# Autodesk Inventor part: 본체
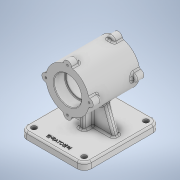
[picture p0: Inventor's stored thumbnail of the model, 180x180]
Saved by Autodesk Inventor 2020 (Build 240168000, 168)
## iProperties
Created: 2022-11
Part Number: 본체
Material: 일반
Document SubType Name: Modeling
Designer: owner
Density: 1 g/cm^3
Appearance: 기본값
Mass: 448.497 g
Surface Area: 803.898 cm^2
Volume: 448.497 cm^3
Author: owner
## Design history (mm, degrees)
sketch "스케치1"
  geometry: L1 (55, 65)-(-55, 65); L2 (-55, 65)-(-55, -65); L3 (-55, -65)-(55, -65); L4 (55, -65)-(55, 65); L5 (55, 65)-(-55, -65); L6 (-55, 65)-(55, -65); 1 further point
  constraints: 12 end point, 2 midpoint, 2 parallel, 1 horizontal, 1 perpendicular
  dimensions: "d0" = 110 distance of L3.end L2.end; "d1" = 130 distance of L2.end L1.end
extrude "돌출1" new body sketch "스케치1" distance "d2" = 12; taper "d3" = 0 deg
node "작업 평면1"
sketch "스케치6"
  geometry: L1 (0, 0)-(110, 0) reference; C1 r 37 at (55, 82); 2 further points
  constraints: 1 centre point, 1 midpoint, 1 vertical alignment
  dimensions: "d20" = 82 distance from line of L1 C1.centre; "d86" = 74 diameter of C1
extrude "돌출4" join sketch "스케치6" stored distance "d21" = 87; taper "d22" = 0 deg
sketch "스케치7"
  geometry: L1 (80.336, 55.036)-(96, 12); L2 (0, 12)-(110, 12) reference; L3 (110, 0)-(110, 12) reference; L4 (29.664, 55.036)-(14, 12); L5 (0, 0)-(0, 12) reference; A1 r 37 centre (55, 82) between (80.336, 55.036) and (29.664, 55.036) reference; 3 further points
  constraints: 4 end point, 2 point on circle
  dimensions: "d23" = 70 deg angle of L2 L1; "d24" = 0 distance from line of L2 L1.end; "d25" = 14 distance from line of L3 L1.end; "d26" = 70 deg angle of L2 L4; "d27" = 14 distance from line of L5 L4.end; "d28" = 0 distance from line of L2 L4.end
extrude "돌출5" join sketch "스케치7" stored distance "d29" = 10; taper "d30" = 0 deg
sketch "스케치9"
  geometry: L1 (14, 12)-(96, 12) reference; L2 (60, 52)-(50, 52); L3 (50, 52)-(50, 12); L4 (50, 12)-(60, 12); L5 (60, 12)-(60, 52); L6 (60, 52)-(50, 12); L7 (50, 52)-(60, 12); A1 r 37 centre (55, 82) between (29.664, 55.036) and (80.336, 55.036) reference; 5 further points
  constraints: 12 end point, 3 midpoint, 2 parallel, 1 horizontal, 1 perpendicular, 1 vertical alignment
  dimensions: "d31" = 10 distance of L4.end L3.end; "d32" = 40 distance of L3.end L2.end; "d33" = 0 distance between parallel lines of L4 L1
extrude "돌출6" join sketch "스케치9" stored distance "d34" = 40; taper "d35" = 0 deg
sketch "스케치10"
  geometry: C1 r 7 at (0, 37); 2 further points
  constraints: 2 vertical alignment, 1 centre point, 1 other
  dimensions: "d36" = 14 diameter of C1
extrude "돌출7" join sketch "스케치10" distance "d37" = 14; taper "d38" = 0 deg
sketch "스케치11"
  geometry: A1 r 7 centre (55, 119) between (61.969, 118.338) and (48.031, 118.338) reference; 2 further points
  constraints: 1 coincident
hole "구멍1" sketch "스케치11" at (55, 119) diameter "d39" = 3.242; stored, may be unused: countersink angle "d43" = 90 deg, drill point angle "d45" = 118 deg; dims "d40" = 8, "d41" = 4, "d42" = 2, "d44" = 10
fillet "모깎기4" dims "d76" = 3
fillet "모깎기5" dims "d77" = 3
sketch "스케치12"
  geometry: A1 r 37 centre (55, 82) between (48.031, 118.338) and (18.662, 88.969) reference; 2 further points
  constraints: 1 coincident
hole "구멍2" sketch "스케치12" at (55, 82) diameter "d49" = 47; stored, may be unused: countersink angle "d53" = 90 deg, drill point angle "d55" = 0 deg; dims "d50" = 8, "d51" = 4, "d52" = 2, "d54" = 19
sketch "스케치13"
  geometry: C1 r 23.5 at (0, 0) reference; 2 further points
  constraints: 1 coincident
hole "구멍3" sketch "스케치13" at (0, 0) diameter "d56" = 42; stored, may be unused: countersink angle "d60" = 90 deg, drill point angle "d62" = 0 deg; dims "d57" = 8, "d58" = 4, "d59" = 2, "d61" = 19
fillet "모깎기1" dims "d63" = 12
sketch "스케치14"
  geometry: A1 r 12 centre (-43, -53) between (-55, -53) and (-43, -65) reference; 2 further points
  constraints: 1 coincident
hole "구멍4" sketch "스케치14" at (-43, -53) diameter "d64" = 9; stored, may be unused: countersink angle "d68" = 90 deg, drill point angle "d70" = 0 deg; dims "d65" = 8, "d66" = 4, "d67" = 2, "d69" = 19
fillet "모깎기2" dims "d71" = 3
fillet "모깎기3" dims "d72" = 1
chamfer "모따기1" distance "d73" = 1; stored, may be unused: second distance "d74" = 2, angle "d75" = 45 deg
fillet "모깎기6" dims "d78" = 3
fillet "모깎기7" dims "d79" = 3
fillet "모깎기8" dims "d80" = 3
fillet "모깎기9" dims "d81" = 3
fillet "모깎기10" dims "d82" = 3
sketch "스케치15"
  geometry: L1 (-55, -53)-(-52, -53) reference; L2 (43, -62)-(-43, -62) reference; 3 further points
  constraints: 1 midpoint, 1 vertical alignment, 1 other
  dimensions: "d83" = 0 distance from line of point (0, -53) L1
feature "엠보싱1" sketch "스케치15" dims "d0" = 110, "d1" = 130, "d24" = 0, "d84" = 0.5, "d85" = 0
sketch "스케치16"
  geometry: 1 further point
node "솔리드1"
pattern_circular "원형 패턴1" dims angle "d47" = 360 deg
mirror "미러1"
mirror "미러2"
mirror "미러3"
feature "A9D066F2-1C7D-4E18-AEED-F7BC21143FA4" dims "d39" = 3.242, "d40" = 8, "d41" = 4, "d42" = 2, "d43" = 90 deg, "d44" = 10, "d45" = 118 deg
